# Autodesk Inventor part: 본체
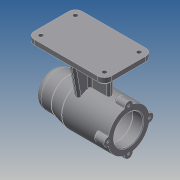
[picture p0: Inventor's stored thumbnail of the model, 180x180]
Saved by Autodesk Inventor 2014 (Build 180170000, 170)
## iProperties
Created: 2019-07
Part Number: 본체
Material: Generic
Document SubType Name: Modeling
Designer: kb542-3
Density: 1 g/cm^3
Appearance: Default
Mass: 238.375 g
Surface Area: 662.537 cm^2
Volume: 238.375 cm^3
Author: kb542-3
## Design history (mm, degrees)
sketch "스케치1"
  geometry: L1 (0, 0)-(112, 0); L2 (0, 0)-(0, 25); L3 (0, 25)-(25, 25); L4 (25, 25)-(45, 30); L5 (45, 30)-(112, 30); L6 (112, 30)-(112, 0)
  constraints: 12 end point, 2 parallel, 2 perpendicular, 1 horizontal
  dimensions: "d0" = 25 distance of L2.end L3.end; "d1" = 45 distance from line of L4.end L2; "d2" = 112 distance between parallel lines of L6 L2; "d3" = 50 diameter of L3 L1; "d4" = 60 diameter of L5 L1
revolve "회전1" sketch "스케치1" stored, may be unused: angle "d5" = 90 deg
sketch "스케치2"
  geometry: L1 (0, 0)-(-112, 0); L2 (-112, 30)-(-112, -30) reference; L3 (-6, 10.5)-(-6, 0); L4 (-6, 10.5)-(-9, 10.5); L5 (-9, 10.5)-(-9, 16); L6 (-9, 16)-(-13, 16); L7 (-13, 16)-(-13, 17.5); L8 (-13, 17.5)-(-31, 17.5); L9 (-31, 17.5)-(-31, 21); L10 (-31, 21)-(-43, 21); L11 (-43, 21)-(-43, 24); L12 (-43, 24)-(-97, 24); L13 (-97, 24)-(-97, 21); L14 (-97, 21)-(-112, 21)
  constraints: 26 end point, 7 perpendicular, 5 parallel, 2 point on line, 1 midpoint
  dimensions: "d6" = 21 diameter of L4 L1; "d7" = 32 diameter of L6 L1; "d8" = 3 distance of L3.start L4.end; "d9" = 4 distance of L5.end L6.end; "d10" = 18 distance of L7.end L8.end; "d11" = 35 diameter of L8 L1; "d12" = 12 distance of L9.end L10.end; "d13" = 42 diameter of L10 L1; "d14" = 54 distance of L11.end L12.end; "d15" = 48 diameter of L12 L1; "d16" = 15 distance of L13.end L14.end; "d17" = 42 diameter of L14 L1
revolve "회전2" sketch "스케치2" stored, may be unused: angle "d18" = 90 deg
sketch "스케치3"
  geometry: C1 r 21 at (0, 0) reference; A1 r 30 centre (0, 0) between (-5.97, 29.4) and (5.97, 29.4) reference; A2 r 6 centre (0, 30) between (5.97, 29.4) and (-5.97, 29.4)
  constraints: 4 point on circle, 1 centre point, 1 vertical alignment
  dimensions: "d19" = 6 radius of A2; "d20" = 30 distance of A2.centre C1.centre
extrude "돌출1" join sketch "스케치3" distance "d21" = 16; taper "d22" = 0 deg
sketch "스케치4"
  geometry: A1 r 6 centre (0, 0) between (5.97, -0.6) and (-5.97, -0.6) reference; 1 further point
  constraints: 1 coincident
hole "구멍1" sketch "스케치4" at (0, 0) diameter "d23" = 3.242; stored, may be unused: countersink angle "d27" = 90 deg, drill point angle "d29" = 118 deg; dims "d24" = 8, "d25" = 4, "d26" = 2, "d28" = 11
fillet "모깎기1" dims "d30" = 3
fillet "모깎기2" dims "d31" = 1
fillet "모깎기12" dims "d88" = 3
sketch "스케치5"
  geometry: L1 (0, 70)-(-112, 70); L2 (-112, 70)-(-112, 80); L3 (-112, 80)-(0, 80); L4 (0, 80)-(0, 70); L5 (0, 25)-(0, -25) reference; L6 (-112, 36)-(-112, 30.171) reference; 1 further point
  constraints: 8 end point, 2 parallel, 1 horizontal, 1 perpendicular, 1 point on line
  dimensions: "d35" = 10 distance of L3.end L1.start; "d36" = 80 distance from line of L3 point (0, 0); "d37" = 112 distance of L2.end L3.end
extrude "돌출2" join sketch "스케치5" stored distance "d38" = 70; taper "d39" = 0 deg
node "작업 평면1"
fillet "모깎기3" dims "d63" = 10
sketch "스케치8"
  geometry: A1 r 10 centre (0, 60) between (0, 70) and (-10, 60) reference; A2 r 10 centre (0, 10) between (-10, 10) and (0, 0) reference; A3 r 10 centre (92, 10) between (92, 0) and (102, 10) reference; A4 r 10 centre (92, 60) between (102, 60) and (92, 70) reference; 5 further points
  constraints: 4 coincident
hole "구멍2" sketch "스케치8" at (0, 60), (0, 10), (92, 10), (92, 60) diameter "d64" = 6; stored, may be unused: countersink angle "d68" = 90 deg, drill point angle "d70" = 118 deg; dims "d65" = 8, "d66" = 4, "d67" = 2, "d69" = 11
chamfer "모따기1" distance "d71" = 3; stored, may be unused: second distance "d72" = 2, angle "d73" = 45 deg
node "작업 평면2"
sketch "스케치9"
  geometry: L1 (-33.5, -6.771)-(-33.5, -29.226) reference; 2 further points
  constraints: 1 horizontal alignment, 1 other
  dimensions: "d74" = 42 distance from line of L1 point (8.5, 0)
feature "엠보싱1" sketch "스케치9" dims "d0" = 25, "d1" = 45, "d2" = 112, "d3" = 50, "d4" = 60, "d6" = 21, "d7" = 32, "d8" = 3, "d9" = 4, "d10" = 18, "d11" = 35, "d12" = 12, "d13" = 42, "d14" = 54, "d15" = 48, "d16" = 15, "d17" = 42, "d75" = 0.5, "d76" = 0
fillet "모깎기4" dims "d77" = 10
fillet "모깎기5" dims "d78" = 3
chamfer "모따기2" distance "d79" = 1; stored, may be unused: second distance "d80" = 2, angle "d81" = 45 deg
fillet "모깎기13" dims "d89" = 3
fillet "모깎기14" dims "d90" = 0.3
fillet "모깎기15" dims "d91" = 3
fillet "모깎기16" dims "d92" = 3
sketch "스케치10"
  geometry: L1 (-100.026, 30)-(-101, 31.621) reference; L2 (-101, 31.621)-(-112, 31.621) reference; L3 (-112, 31.621)-(-112, 36) reference; L4 (-112, 36)-(-99, 36) reference; L5 (-96, 33)-(-96, 31) reference; L6 (-95, 30)-(-45.369, 30) reference; L7 (-44.642, 29.91)-(-25.358, 25.09) reference; L8 (-24.631, 25)-(-10, 25) reference; L9 (0, 15)-(0, -15) reference; L10 (-10, -25)-(-24.631, -25) reference; L11 (-25.358, -25.09)-(-44.642, -29.91) reference; L12 (-45.369, -30)-(-95, -30) reference; L13 (-96, -31)-(-96, -33) reference; L14 (-99, -36)-(-112, -36) reference; L15 (-112, -36)-(-112, -31.621) reference; L16 (-112, -31.621)-(-101, -31.621) reference; L17 (-101, -31.621)-(-100.026, -30) reference; L18 (-100.026, -30)-(-101, -28.379) reference; L19 (-101, -28.379)-(-112, -28.379) reference; L20 (-112, -28.379)-(-112, -22) reference; L21 (-112, -22)-(-111, -21) reference; L22 (-111, -21)-(-97, -21) reference; L23 (-94, -24)-(-46, -24) reference; L24 (-43, -21)-(-31.3, -21) reference; L25 (-31, -20.7)-(-31, -17.5) reference; L26 (-31, -17.5)-(-13.3, -17.5) reference; L27 (-13, -17.2)-(-13, -16) reference; L28 (-13, -16)-(-9.3, -16) reference; L29 (-9, -15.7)-(-9, -10.5) reference; L30 (-6, -7.5)-(-6, 7.5) reference; L31 (-9, 10.5)-(-9, 15.7) reference; L32 (-9.3, 16)-(-13, 16) reference; L33 (-13, 16)-(-13, 17.2) reference; L34 (-13.3, 17.5)-(-31, 17.5) reference; L35 (-31, 17.5)-(-31, 20.7) reference; L36 (-31.3, 21)-(-43, 21) reference; L37 (-46, 24)-(-94, 24) reference; L38 (-97, 21)-(-111, 21) reference; L39 (-111, 21)-(-112, 22) reference; L40 (-112, 22)-(-112, 28.379) reference; L41 (-112, 28.379)-(-101, 28.379) reference; L42 (-101, 28.379)-(-100.026, 30) reference; L43 (-109, 70)-(-112, 73) reference; L44 (-112, 73)-(-112, 80) reference; L45 (-112, 80)-(0, 80) reference; L46 (0, 80)-(0, 73) reference; L47 (0, 73)-(-3, 70) reference; L48 (-3, 70)-(-109, 70) reference; L49 (-87, 30)-(-87, 70); L50 (-10, 70)-(-102, 70) reference; L51 (-35.43, 27.607)-(-20, 70); A1 r 3 centre (-99, 33) between (-96, 33) and (-99, 36) reference; A2 r 1 centre (-95, 31) between (-96, 31) and (-95, 30) reference; A3 r 3 centre (-45.369, 27) between (-44.642, 29.91) and (-45.369, 30) reference; A4 r 3 centre (-24.631, 28) between (-25.358, 25.09) and (-24.631, 25) reference; A5 r 10 centre (-10, 15) between (0, 15) and (-10, 25) reference; A6 r 10 centre (-10, -15) between (-10, -25) and (0, -15) reference; A7 r 3 centre (-24.631, -28) between (-24.631, -25) and (-25.358, -25.09) reference; A8 r 3 centre (-45.369, -27) between (-45.369, -30) and (-44.642, -29.91) reference; A9 r 1 centre (-95, -31) between (-95, -30) and (-96, -31) reference; A10 r 3 centre (-99, -33) between (-99, -36) and (-96, -33) reference; A11 r 3 centre (-94, -21) between (-97, -21) and (-94, -24) reference; A12 r 3 centre (-46, -21) between (-46, -24) and (-43, -21) reference; A13 r 0.3 centre (-31.3, -20.7) between (-31.3, -21) and (-31, -20.7) reference; A14 r 0.3 centre (-13.3, -17.2) between (-13.3, -17.5) and (-13, -17.2) reference; A15 r 0.3 centre (-9.3, -15.7) between (-9.3, -16) and (-9, -15.7) reference; A16 r 3 centre (-9, -7.5) between (-9, -10.5) and (-6, -7.5) reference; A17 r 3 centre (-9, 7.5) between (-6, 7.5) and (-9, 10.5) reference; A18 r 0.3 centre (-9.3, 15.7) between (-9, 15.7) and (-9.3, 16) reference; A19 r 0.3 centre (-13.3, 17.2) between (-13, 17.2) and (-13.3, 17.5) reference; A20 r 0.3 centre (-31.3, 20.7) between (-31, 20.7) and (-31.3, 21) reference; A21 r 3 centre (-46, 21) between (-43, 21) and (-46, 24) reference; A22 r 3 centre (-94, 21) between (-94, 24) and (-97, 21) reference; 1 further point
  constraints: 4 end point, 4 point on line, 1 perpendicular
  dimensions: "d93" = 20 horizontal distance of L45.end L51.end; "d94" = 25 distance between parallel lines of L44 L49; "d95" = 110 deg angle of L50 L51
extrude "돌출4" join sketch "스케치10" stored distance "d96" = 8; taper "d97" = 0 deg
node "작업 평면3"
sketch "스케치11"
  geometry: L1 (25, 70)-(-25, 70) reference; L2 (-28, 70)-(-19.654, 22.666); L3 (28, 70)-(19.654, 22.666); L4 (-35, 73)-(-35, 80) reference; L5 (35, 80)-(35, 73) reference; L6 (30.493, -0.648)-(29.993, -0.648) reference; L7 (0, 30)-(-4, 30) reference; L8 (-4, 30)-(-4, 70) reference; L9 (-4, 70)-(-32, 70) reference; L10 (-32, 70)-(-35, 73) reference; L11 (-35, 73)-(-35, 80) reference; L12 (-35, 80)-(35, 80) reference; L13 (35, 80)-(35, 73) reference; L14 (35, 73)-(32, 70) reference; L15 (32, 70)-(4, 70) reference; L16 (4, 70)-(4, 30) reference; L17 (4, 30)-(0, 30) reference; L18 (29.999, -0.254)-(30.499, -0.254) reference; C1 r 24 at (0, 0) reference; A1 r 30 centre (0, 0) between (0, 30) and (19.654, 22.666) reference; A2 r 30 centre (0, 0) between (29.999, -0.254) and (0, 30) reference; A3 r 30 centre (0, 0) between (0, 30) and (29.993, -0.648) reference; A4 r 30.5 centre (0, 0) between (30.493, -0.648) and (30.499, -0.254) reference; 1 further point
  constraints: 4 end point, 2 point on circle, 2 point on line
  dimensions: "d99" = 7 distance from line of L2.start L4; "d100" = 7 distance from line of L3.start L5; "d101" = 100 deg angle of L15 L3; "d102" = 100 deg angle of L2 L9
  node "절단 모서리 투영2"
feature "리브3" dims "d103" = 1, "d104" = 8, "d105" = 0, "d106" = 0, "d107" = 1, "d108" = 1
feature "리브4" dims "d109" = 1, "d110" = 8, "d111" = 0, "d112" = 0, "d113" = 1, "d114" = 1
fillet "모깎기17" dims "d115" = 3
fillet "모깎기18" dims "d116" = 3
fillet "모깎기19" dims "d117" = 3
node "솔리드1"
pattern_circular "원형 패턴1" dims "d33" = 360 deg
node "절단 모서리 투영1"
other parameters: "d46" = 56, "d98" = 56
